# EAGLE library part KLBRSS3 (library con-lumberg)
Jack connectors according to JISC 6560, 6.35 mm Klinkeneinbaukupplung nach JISC 6560, 6,35 mm, 3-polig/stereo, abgewinkelte Ausführung, mit 2 Umschaltern, Leiterplatten Rückseitenmontage Source: http://www.lumberg.de/Produkte/PDFs/KLBRSS3.pdf
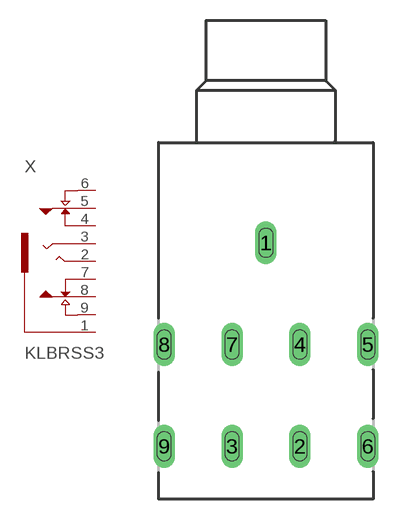
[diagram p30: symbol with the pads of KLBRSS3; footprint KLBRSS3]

Designator prefix X

## KLBRSS3 (OC_FARNELL: 1200145; OC_NEWARK: unknown)  [KLBRSS3]
1  1  pas
2  2  pas
3  3  pas
4  4  pas
5  5  pas
6  6  pas
7  7  pas
8  8  pas
9  9  pas

## Footprint KLBRSS3 (pad centres in mm)
Jack connectors according to JISC 6560, 6.35 mm Klinkeneinbaukupplung nach JISC 6560, 6,35 mm, 3-polig/stereo, abgewinkelte Ausführung, mit 2 Umschaltern, Leiterplatten Rückseitenmontage Source: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
drill 1 pad 1.6 long: 1 0,-7.5; 2 2.5,-22.5; 3 -2.5,-22.5; 4 2.5,-15; 5 7.5,-15; 6 7.5,-22.5; 7 -2.5,-15; 8 -7.5,-15; 9 -7.5,-22.5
